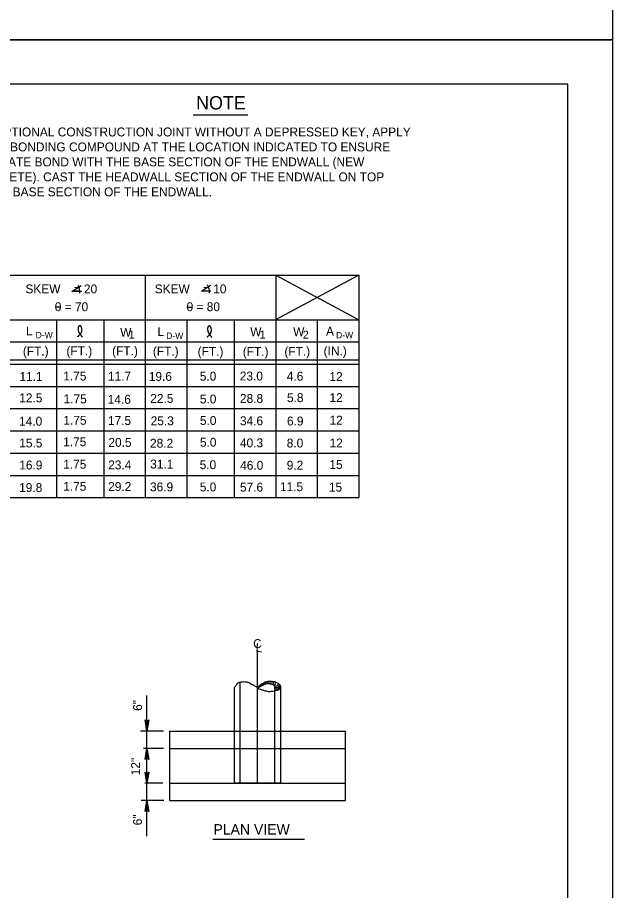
# Model space of a CAD drawing. Extents: x 638877 to 639960, y 297341 to 299123.
# Drawn here: x 639517.9 to 639718.2, y 297649 to 297942.8 of the extents above; entities that cross this region are included whole.
import ezdxf

# ---------------------------------------------------------------- set-up
doc = ezdxf.new("R2010")
doc.units = 0
for name, color, linetype in [('1', 7, 'Continuous'), ('2', 7, 'Continuous'), ('3', 7, 'Continuous'), ('PLT-BNDY', 7, 'Continuous')]:
    doc.layers.add(name, color=color, linetype=linetype)

msp = doc.modelspace()

# ---------------------------------------------------------------- linework, layer by layer
at = {"layer": '1'}
for p, q in [((639703.19, 297920.28), (638917.19, 297920.28)), ((639703.19, 297356.28), (639703.19, 297920.28)), ((639577.08, 297909.96), (639595.45, 297909.96)), ((639579.94, 297909.96), (639592.68, 297909.96)), ((639598.72, 297685.09), (639598.72, 297729.98))]:
    msp.add_line(p, q, dxfattribs=at)
at = {"layer": '2'}
for p, q in [((639590.92, 297696.79), (639590.92, 297717.22)), ((639592.87, 297685.09), (639592.87, 297718.96)), ((639604.57, 297685.09), (639604.57, 297716.2)), ((639606.52, 297696.79), (639606.52, 297717.22)), ((639561.48, 297702.64), (639561.48, 297714.62)), ((639567.07, 297702.64), (639559.35, 297702.64)), ((639561.48, 297679.24), (639561.48, 297702.64)), ((639569.14, 297702.64), (639628.29, 297702.64)), ((639569.14, 297679.24), (639569.14, 297702.64)), ((639628.29, 297679.24), (639628.29, 297702.64)), ((639567.07, 297696.79), (639560.33, 297696.79)), ((639569.14, 297696.79), (639628.29, 297696.79)), ((639590.92, 297685.09), (639590.92, 297696.79)), ((639606.52, 297685.09), (639606.52, 297696.79)), ((639566.79, 297685.09), (639560.79, 297685.09)), ((639569.14, 297685.09), (639628.29, 297685.09)), ((639606.52, 297685.09), (639590.92, 297685.09)), ((639567.21, 297679.24), (639559.49, 297679.24)), ((639561.48, 297667.26), (639561.48, 297679.24)), ((639569.14, 297679.24), (639628.29, 297679.24))]:
    msp.add_line(p, q, dxfattribs=at)
for points in [[(639561.93, 297706.18), (639561.67, 297706.05), (639561.48, 297702.64), (639561.93, 297706.18), (639562.08, 297706.36), (639561.48, 297702.64), (639561.31, 297706.05), (639561.06, 297706.17), (639561.48, 297702.64), (639560.89, 297706.36), (639561.06, 297706.17)], [(639561.04, 297693.25), (639561.3, 297693.38), (639561.48, 297696.79), (639561.04, 297693.25), (639560.88, 297693.07), (639561.48, 297696.79), (639561.65, 297693.38), (639561.9, 297693.26), (639561.48, 297696.79), (639562.08, 297693.07), (639561.9, 297693.26)], [(639561.93, 297688.63), (639561.67, 297688.5), (639561.48, 297685.09), (639561.93, 297688.63), (639562.08, 297688.81), (639561.48, 297685.09), (639561.31, 297688.5), (639561.06, 297688.62), (639561.48, 297685.09), (639560.89, 297688.81), (639561.06, 297688.62)], [(639561.04, 297675.7), (639561.3, 297675.83), (639561.48, 297679.24), (639561.04, 297675.7), (639560.88, 297675.52), (639561.48, 297679.24), (639561.65, 297675.83), (639561.9, 297675.71), (639561.48, 297679.24), (639562.08, 297675.52), (639561.9, 297675.71)]]:
    msp.add_lwpolyline(points, dxfattribs=at)
for centre, radius, start, end in [((639602.27, 297718.87), 0.315, 302.411, 76.6825), ((639602.98, 297718.92), 0.359, 289.7004, 78.5016), ((639603.64, 297718.8), 0.415, 261.0795, 65.4873), ((639599.32, 297717.58), 0.127, 266.947, 183.053), ((639599.46, 297717.69), 0.298, 15.6074, 55.806), ((639600.08, 297718.08), 0.173, 285.7562, 123.8551), ((639600.6, 297718.4), 0.174, 293.3341, 133.8053), ((639601.18, 297718.66), 0.253, 278.5457, 142.8367), ((639601.68, 297718.74), 0.291, 313.7085, 92.3299), ((639604.13, 297718.84), 0.667, 263.2089, 8.5784), ((639604.67, 297718.98), 1.18, 254.8508, 332.5231), ((639605.05, 297718.49), 1.18, 248.8965, 335.9336), ((639605.03, 297718.5), 1.67, 258.491, 327.5129)]:
    msp.add_arc(centre, radius, start, end, dxfattribs=at)
for points in [[(639590.92, 297717.22), (639591.26, 297717.72), (639591.6, 297718.24), (639592.24, 297718.82), (639593.19, 297719.17), (639594.98, 297719.2), (639595.95, 297718.91), (639596.67, 297718.46), (639597.43, 297718.05), (639597.96, 297717.74), (639598.41, 297717.48), (639598.72, 297717.22), (639599.31, 297716.82), (639599.93, 297716.58), (639600.96, 297716.27), (639601.58, 297716.12), (639602.31, 297716), (639602.86, 297716), (639603.79, 297716.08), (639604.77, 297716.27), (639605.48, 297716.43), (639606.22, 297716.79), (639606.52, 297717.22), (639606.48, 297717.77), (639606.03, 297718.29), (639605.51, 297718.72), (639604.89, 297719.01), (639604.08, 297719.24), (639603.1, 297719.32), (639602.29, 297719.29), (639601.29, 297719.03), (639600.55, 297718.65), (639599.89, 297718.29), (639599.36, 297717.84), (639598.72, 297717.22)], [(639604.57, 297716.2), (639604.6, 297716.67), (639604.55, 297717.29), (639604.51, 297717.62), (639604.27, 297717.89), (639604.08, 297718.08), (639603.77, 297718.27), (639603.34, 297718.41), (639602.89, 297718.51), (639602.39, 297718.53), (639601.96, 297718.53), (639601.51, 297718.44), (639601.08, 297718.34), (639600.77, 297718.17), (639600.22, 297717.86), (639599.96, 297717.77), (639599.72, 297717.67), (639599.31, 297717.41), (639599.03, 297717.29), (639598.72, 297717.22)]]:
    msp.add_spline(points, degree=3, dxfattribs=at)
at = {"layer": '3'}
for p, q in [((639233.8, 297856.01), (639632.75, 297856.01)), ((639560.94, 297856.01), (639560.94, 297781.21)), ((639632.75, 297856.01), (639604.78, 297841.04)), ((639604.82, 297856.01), (639604.82, 297781.21)), ((639604.82, 297856.01), (639632.75, 297841.05)), ((639632.75, 297856.01), (639632.75, 297781.21)), ((639536.25, 297850.51), (639539.33, 297852.55)), ((639579.83, 297850.68), (639582.91, 297852.72)), ((639539.46, 297850.51), (639536.25, 297850.51)), ((639583.03, 297850.68), (639579.83, 297850.68)), ((639530.54, 297845.36), (639532.48, 297845.36)), ((639574.86, 297845.34), (639576.8, 297845.34)), ((639233.8, 297841.05), (639632.75, 297841.05)), ((639531.02, 297841.05), (639531.02, 297781.21)), ((639546.97, 297841.05), (639546.97, 297781.21)), ((639574.9, 297841.05), (639574.9, 297781.21)), ((639590.86, 297841.05), (639590.86, 297781.21)), ((639618.79, 297841.05), (639618.79, 297781.21)), ((639233.8, 297833.57), (639632.75, 297833.57)), ((639233.8, 297827.59), (639632.75, 297827.59)), ((639233.8, 297826.09), (639632.75, 297826.09)), ((639233.8, 297818.61), (639632.75, 297818.61)), ((639233.8, 297811.13), (639632.75, 297811.13)), ((639233.8, 297803.65), (639632.75, 297803.65)), ((639233.8, 297796.17), (639632.75, 297796.17)), ((639233.8, 297788.69), (639632.75, 297788.69)), ((639233.8, 297781.21), (639632.75, 297781.21)), ((639583.71, 297666.2), (639614.49, 297666.2))]:
    msp.add_line(p, q, dxfattribs=at)
for centre in [(639534.88, 297850.37), (639578.45, 297850.53)]:
    msp.add_arc(centre, 4.07, 354.1715, 33.0785, dxfattribs=at)
for points in [[(639538.17, 297835.34), (639538.33, 297835.48), (639538.43, 297835.58), (639538.59, 297835.74), (639538.72, 297835.87), (639538.94, 297836.04), (639539.1, 297836.24), (639539.24, 297836.39), (639539.34, 297836.58), (639539.42, 297836.78), (639539.48, 297836.96), (639539.55, 297837.15), (639539.57, 297837.3), (639539.6, 297837.5), (639539.61, 297837.68), (639539.6, 297837.87), (639539.56, 297838.07), (639539.52, 297838.27), (639539.47, 297838.45), (639539.4, 297838.63), (639539.35, 297838.74), (639539.27, 297838.82), (639539.19, 297838.9), (639539.12, 297838.97), (639539.03, 297839.01), (639538.96, 297839.03), (639538.82, 297839.03), (639538.75, 297839.01), (639538.63, 297838.97), (639538.55, 297838.91), (639538.51, 297838.84), (639538.46, 297838.74), (639538.4, 297838.65), (639538.37, 297838.54), (639538.34, 297838.45), (639538.31, 297838.26), (639538.29, 297838.13), (639538.31, 297837.97), (639538.31, 297837.81), (639538.34, 297837.59), (639538.36, 297837.41), (639538.39, 297837.27), (639538.45, 297837.1), (639538.52, 297836.92), (639538.6, 297836.76), (639538.68, 297836.6), (639538.77, 297836.42), (639538.93, 297836.28), (639539.03, 297836.11), (639539.14, 297835.99), (639539.22, 297835.84), (639539.34, 297835.71), (639539.44, 297835.57), (639539.53, 297835.48), (639539.62, 297835.38), (639539.7, 297835.24)], [(639581.75, 297835.26), (639581.92, 297835.4), (639582.01, 297835.5), (639582.18, 297835.66), (639582.3, 297835.79), (639582.52, 297835.96), (639582.68, 297836.16), (639582.83, 297836.32), (639582.92, 297836.5), (639583.01, 297836.7), (639583.07, 297836.88), (639583.13, 297837.07), (639583.15, 297837.22), (639583.18, 297837.43), (639583.19, 297837.6), (639583.18, 297837.79), (639583.14, 297838), (639583.11, 297838.19), (639583.06, 297838.37), (639582.99, 297838.56), (639582.93, 297838.66), (639582.85, 297838.74), (639582.78, 297838.82), (639582.7, 297838.89), (639582.61, 297838.93), (639582.54, 297838.95), (639582.41, 297838.95), (639582.33, 297838.93), (639582.22, 297838.89), (639582.14, 297838.83), (639582.09, 297838.76), (639582.04, 297838.66), (639581.98, 297838.57), (639581.95, 297838.46), (639581.93, 297838.37), (639581.9, 297838.18), (639581.88, 297838.05), (639581.9, 297837.89), (639581.9, 297837.73), (639581.93, 297837.51), (639581.95, 297837.33), (639581.97, 297837.19), (639582.03, 297837.02), (639582.11, 297836.84), (639582.19, 297836.68), (639582.26, 297836.53), (639582.36, 297836.34), (639582.51, 297836.2), (639582.61, 297836.03), (639582.72, 297835.91), (639582.81, 297835.76), (639582.92, 297835.63), (639583.03, 297835.49), (639583.11, 297835.41), (639583.2, 297835.3), (639583.29, 297835.16)]]:
    msp.add_spline(points, degree=3, dxfattribs=at)
at = {"layer": 'PLT-BNDY'}
for points in [[(638877.19, 298529.28), (639718.19, 298529.28), (639718.19, 297935.28), (638877.19, 297935.28)], [(638877.19, 297935.28), (639718.19, 297935.28), (639718.19, 297341.28), (638877.19, 297341.28)]]:
    msp.add_lwpolyline(points, close=True, dxfattribs=at)

# ---------------------------------------------------------------- texts
at = {"layer": '1'}
for s, height, p in [('FOR OPTIONAL CONSTRUCTION JOINT WITHOUT A DEPRESSED KEY, APPLY ', 3, (639500.47, 297902.75)), ('EPOXY BONDING COMPOUND AT THE LOCATION INDICATED TO ENSURE ', 3, (639500.47, 297897.71)), ('ADEQUATE BOND WITH THE BASE SECTION OF THE ENDWALL (NEW ', 3, (639500.47, 297892.67)), ('CONCRETE). CAST THE HEADWALL SECTION OF THE ENDWALL ON TOP ', 3, (639500.47, 297887.63)), ('OF THE BASE SECTION OF THE ENDWALL.', 3, (639500.47, 297882.59)), ('D-W', 2.154, (639524.01, 297834.82)), ('D-W', 2.154, (639567.96, 297834.57)), ('D-W', 2.154, (639625.13, 297834.81))]:
    msp.add_text(s, height=height, dxfattribs=at).set_placement(p)
for s, rotation, p in [('C', 5, (639597.37, 297730.42)), ('L', 357, (639598, 297729.26))]:
    msp.add_text(s, height=3, rotation=rotation, dxfattribs=at).set_placement(p)
at = {"layer": '3'}
for s, height, p in [('NOTE', 4.5, (639578.04, 297911.81)), ('SKEW    = 20', 2.9921, (639520.6, 297849.94)), ('SKEW    = 10', 2.9921, (639564.12, 297849.94)), ('0 = 70', 2.992, (639530.47, 297843.94)), ('0 = 80', 2.992, (639574.83, 297843.94)), ('L', 2.99, (639520.79, 297835.78)), ('W', 2.99, (639552.48, 297835.32)), ('1', 2.7, (639555.34, 297834.72)), ('L', 2.99, (639565.04, 297835.56)), ('W', 2.99, (639596.26, 297835.52)), ('1', 2.7, (639599.4, 297834.73)), ('W', 2.99, (639610.7, 297835.5)), ('2', 2.69, (639613.95, 297834.68)), ('A', 2.99, (639621.75, 297835.7)), ('(FT.)', 2.992, (639519.73, 297829.02)), ('(FT.)', 2.992, (639534.39, 297829.09)), ('(FT.)', 2.992, (639549.77, 297829.09)), ('(FT.)', 2.992, (639563.48, 297829)), ('(FT.)', 2.992, (639578.55, 297828.94)), ('(FT.)', 2.992, (639593.74, 297828.85)), ('(FT.)', 2.992, (639607.74, 297828.93)), ('(IN.)', 2.992, (639620.95, 297829.11)), ('11.1', 2.992, (639518.58, 297820.48)), ('1.75', 2.992, (639533.33, 297820.61)), ('11.7', 2.992, (639548.35, 297820.56)), ('19.6', 2.992, (639562.11, 297820.48)), ('5.0', 2.992, (639579.27, 297820.55)), ('23.0', 2.992, (639592.73, 297820.61)), ('4.6', 2.992, (639608.56, 297820.56)), ('12', 2.992, (639622.9, 297820.43)), ('12.5', 2.992, (639518.51, 297813.26)), ('22.5', 2.992, (639562.6, 297813.07)), ('28.8', 2.992, (639592.79, 297813.06)), ('5.8', 2.992, (639608.61, 297813.34)), ('12', 2.992, (639622.92, 297813.34)), ('1.75', 2.992, (639533.43, 297812.92)), ('14.6', 2.992, (639548.29, 297812.77)), ('5.0', 2.992, (639579.3, 297812.88)), ('14.0', 2.992, (639518.45, 297805.41)), ('1.75', 2.992, (639533.36, 297805.72)), ('17.5', 2.992, (639548.36, 297805.63)), ('25.3', 2.992, (639562.74, 297805.55)), ('5.0', 2.992, (639579.32, 297805.64)), ('34.6', 2.992, (639592.79, 297805.55)), ('6.9', 2.992, (639608.61, 297805.48)), ('12', 2.992, (639622.94, 297805.77)), ('1.75', 2.992, (639533.29, 297798.5)), ('15.5', 2.992, (639518.51, 297798.08)), ('20.5', 2.992, (639548.51, 297798.28)), ('28.2', 2.992, (639562.53, 297798)), ('5.0', 2.992, (639579.32, 297798.33)), ('40.3', 2.992, (639592.79, 297798.13)), ('8.0', 2.992, (639608.54, 297798.06)), ('12', 2.992, (639622.94, 297798.08)), ('16.9', 2.992, (639518.51, 297790.66)), ('1.75', 2.992, (639533.31, 297790.92)), ('23.4', 2.992, (639548.44, 297790.71)), ('31.1', 2.992, (639562.58, 297790.99)), ('5.0', 2.992, (639579.23, 297790.77)), ('46.0', 2.992, (639592.86, 297790.57)), ('9.2', 2.992, (639608.54, 297790.62)), ('15', 2.992, (639622.9, 297790.84)), ('19.8', 2.992, (639518.47, 297783.09)), ('1.75', 2.992, (639533.31, 297783.5)), ('29.2', 2.992, (639548.44, 297783.44)), ('36.9', 2.992, (639562.51, 297783.3)), ('5.0', 2.992, (639579.27, 297783.28)), ('57.6', 2.992, (639592.79, 297783.21)), ('11.5', 2.992, (639606.26, 297783.37)), ('15', 2.992, (639622.72, 297783.22)), ('PLAN VIEW', 3.53, (639583.86, 297667.77))]:
    msp.add_text(s, height=height, dxfattribs=at).set_placement(p)
for s, p in [('6"', (639559.83, 297709.43)), ('12"', (639559.18, 297687.74)), ('6"', (639559.83, 297670.91))]:
    msp.add_text(s, height=3, rotation=90, dxfattribs=at).set_placement(p)

doc.saveas('drawing.dxf')
